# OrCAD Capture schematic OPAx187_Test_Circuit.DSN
size A; title: OPAx187 0.001-µV/°C Drift, Low Power, Rail-to-Rail Output 36-V; rev: 1.4; note: Datasheet: SBOS807E   EVM: N/A
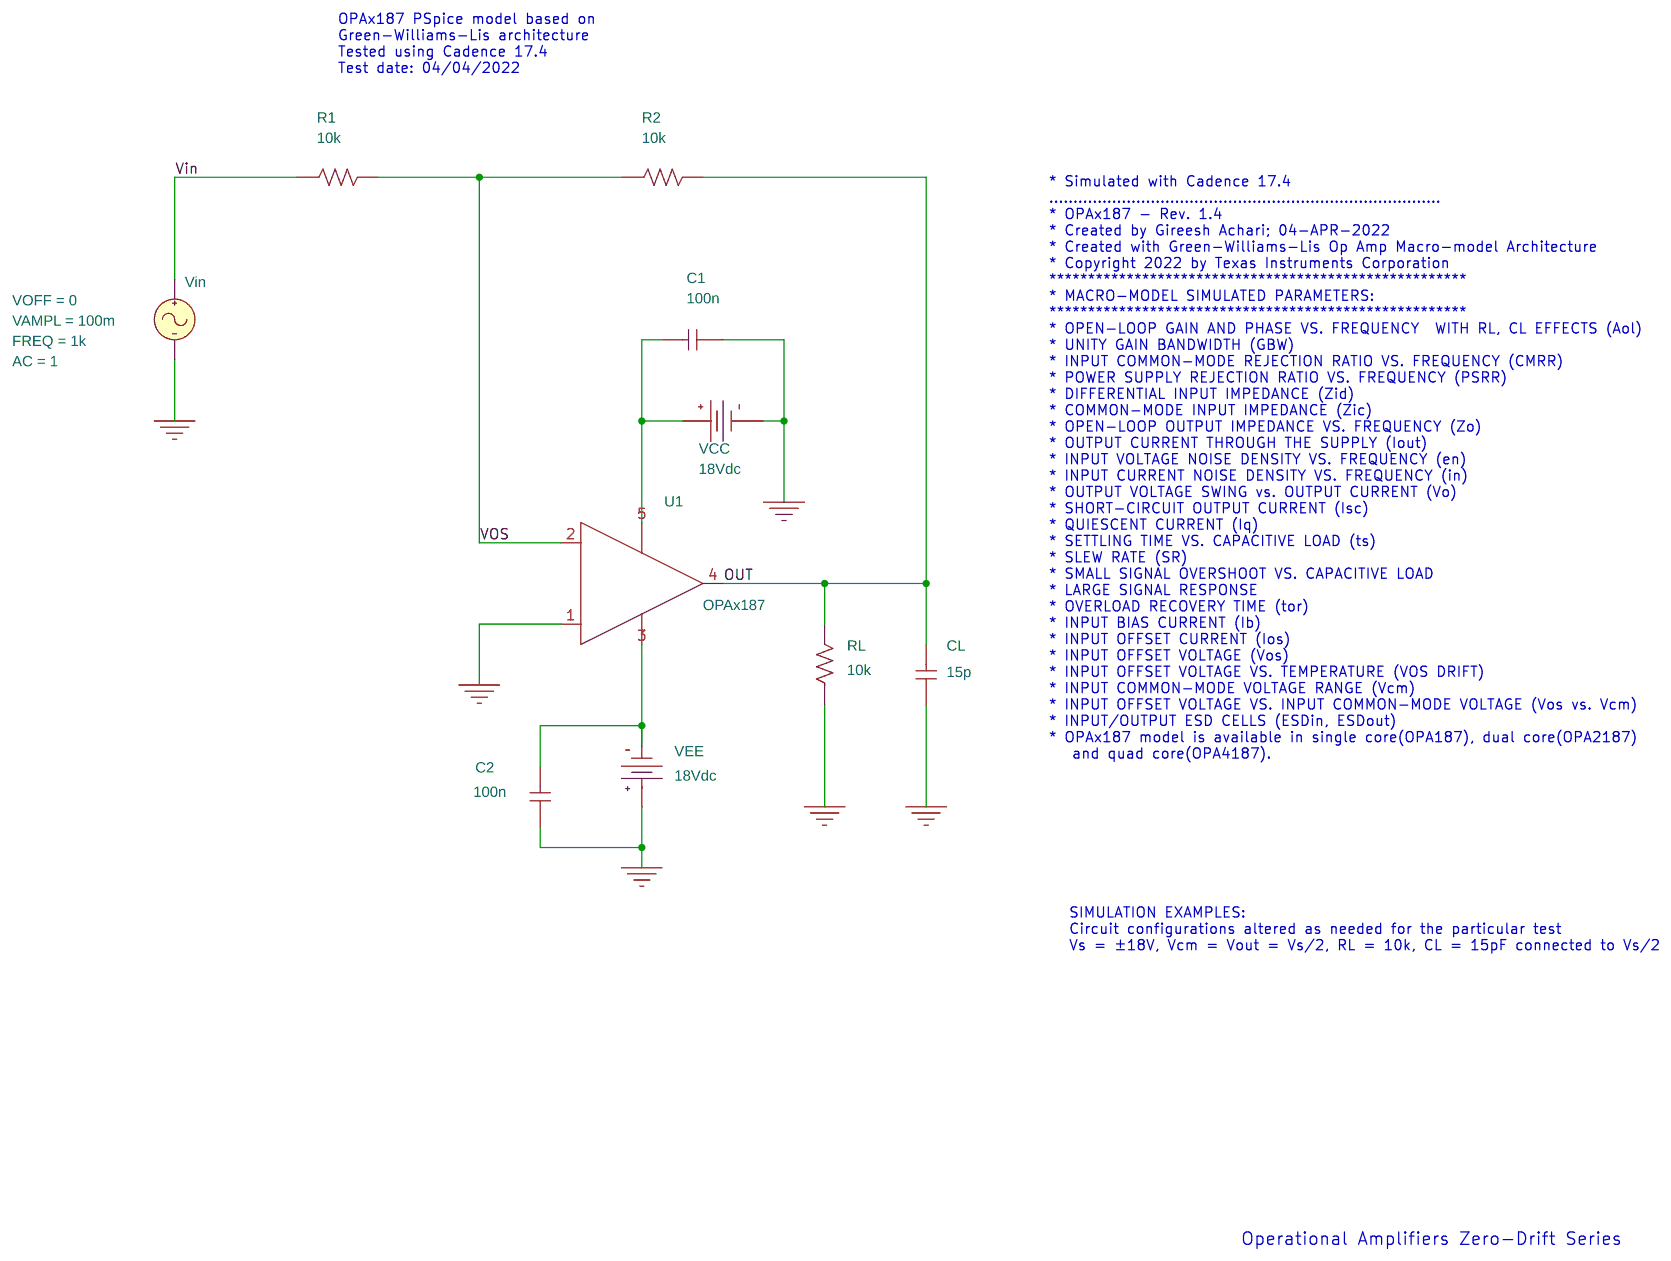
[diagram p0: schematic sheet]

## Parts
C1  100n  [cap196]
C2  100n  [cap196]
CL  15p  [cap196]
R1  10k  [AXRC05]
R2  10k  [AXRC05]
RL  10k  [AXRC05]
U1  OPAx187
VCC  VDC
VEE  VDC
Vin  VSIN

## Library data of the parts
C1 C2 CL = C
R1 R2 RL = R
U1 = OPAx187
VCC VEE = VDC: DC: 18Vdc
Vin = VSIN: AC: 1; FREQ: 1k; VAMPL: 100m; VOFF: 0

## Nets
Vin: R1.1 Vin.1(+)
0: C1.2 C2.1 CL.2 RL.1 U1.1(+) VCC.1(-) VEE.0(+) Vin.2(-)
OUT: CL.1 R2.2 RL.2 U1.4(OUT)
VOS: R1.2 R2.1 U1.2(-)
N27303: C1.1 U1.5(V+) VCC.0(+)
N27354: C2.2 U1.3(V-) VEE.1(-)

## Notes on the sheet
- OPAx187 PSpice model based on
  Green-Williams-Lis architecture
  Tested using Cadence 17.4
  Test date: 04/04/2022
- * Simulated with Cadence 17.4
  .................................................................................
  * OPAx187 - Rev. 1.4
  * Created by Gireesh Achari; 04-APR-2022
  * Created with Green-Williams-Lis Op Amp Macro-model Architecture
  * Copyright 2022 by Texas Instruments Corporation
  ******************************************************
  * MACRO-MODEL SIMULATED PARAMETERS:
  ******************************************************
  * OPEN-LOOP GAIN AND PHASE VS. FREQUENCY  WITH RL, CL EFFECTS (Aol)
  * UNITY GAIN BANDWIDTH (GBW)
  * INPUT COMMON-MODE REJECTION RATIO VS. FREQUENCY (CMRR)
  * POWER SUPPLY REJECTION RATIO VS. FREQUENCY (PSRR)
  * DIFFERENTIAL INPUT IMPEDANCE (Zid)
  * COMMON-MODE INPUT IMPEDANCE (Zic)
  * OPEN-LOOP OUTPUT IMPEDANCE VS. FREQUENCY (Zo)
  * OUTPUT CURRENT THROUGH THE SUPPLY (Iout)
  * INPUT VOLTAGE NOISE DENSITY VS. FREQUENCY (en)
  * INPUT CURRENT NOISE DENSITY VS. FREQUENCY (in)
  * OUTPUT VOLTAGE SWING vs. OUTPUT CURRENT (Vo)
  * SHORT-CIRCUIT OUTPUT CURRENT (Isc)
  * QUIESCENT CURRENT (Iq)
  * SETTLING TIME VS. CAPACITIVE LOAD (ts)
  * SLEW RATE (SR)
  * SMALL SIGNAL OVERSHOOT VS. CAPACITIVE LOAD
  * LARGE SIGNAL RESPONSE
  * OVERLOAD RECOVERY TIME (tor)
  * INPUT BIAS CURRENT (Ib)
  * INPUT OFFSET CURRENT (Ios)
  * INPUT OFFSET VOLTAGE (Vos)
  * INPUT OFFSET VOLTAGE VS. TEMPERATURE (VOS DRIFT)
  * INPUT COMMON-MODE VOLTAGE RANGE (Vcm)
  * INPUT OFFSET VOLTAGE VS. INPUT COMMON-MODE VOLTAGE (Vos vs. Vcm)
  * INPUT/OUTPUT ESD CELLS (ESDin, ESDout)
  * OPAx187 model is available in single core(OPA187), dual core(OPA2187)
     and quad core(OPA4187).
- SIMULATION EXAMPLES:
  Circuit configurations altered as needed for the particular test
  Vs = ±18V, Vcm = Vout = Vs/2, RL = 10k, CL = 15pF connected to Vs/2
- Operational Amplifiers Zero-Drift Series
